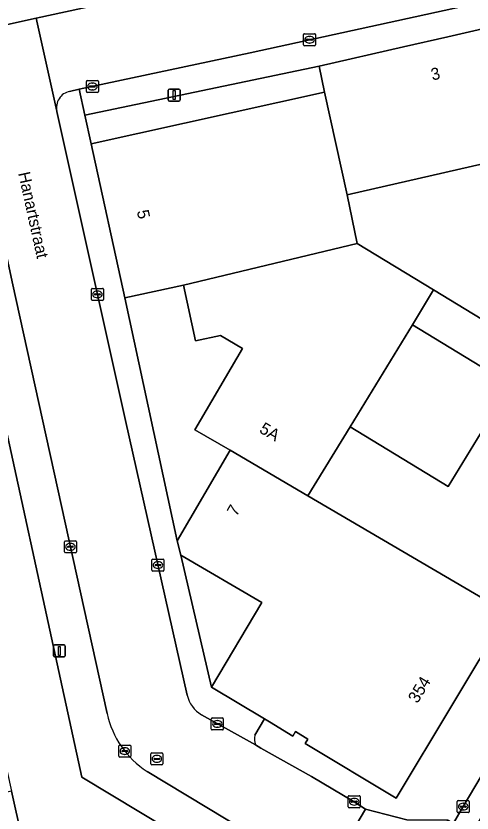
# Model space of a CAD drawing. Extents: x 160554 to 161248, y 385329 to 386506.
# Drawn here: x 160800.8 to 160838.9, y 385796.5 to 385863.1 of the extents above; entities that cross this region are included whole.
import ezdxf

# ---------------------------------------------------------------- set-up
doc = ezdxf.new("R2010")
doc.units = 0
for name, color, linetype in [('IMGEO_Erf', 7, 'Continuous'), ('IMGEO_Kolk', 7, 'Continuous'), ('IMGEO_Lichtmast', 7, 'Continuous'), ('IMGEO_Openbare_ruimte_label', 7, 'Continuous'), ('IMGEO_Pand', 7, 'Continuous'), ('IMGEO_Pand_nummerreeks', 7, 'Continuous'), ('IMGEO_Parkeervlak_open', 7, 'Continuous'), ('IMGEO_Rijbaan_lokaal_gesloten', 7, 'Continuous'), ('IMGEO_Rijbaan_lokaal_open', 7, 'Continuous'), ('IMGEO_Rioolput', 7, 'Continuous'), ('IMGEO_Voetpad_open', 7, 'Continuous')]:
    doc.layers.add(name, color=color, linetype=linetype)

msp = doc.modelspace()

# ---------------------------------------------------------------- linework, layer by layer
at = {"layer": 'IMGEO_Erf'}
for points in [[(160807.109, 385852.398), (160826.584, 385856.714), (160826.13, 385858.866), (160806.576, 385854.787)], [(160797.582, 385839.533), (160777.43, 385835.122), (160782.162, 385813.51), (160796.35, 385816.614), (160798.295, 385807.928), (160800.447, 385798.314), (160802.235, 385790.33), (160796.019, 385788.976), (160795.316, 385792.204), (160792.549, 385791.601), (160793.252, 385788.373), (160788.797, 385787.403), (160789.812, 385782.742), (160805.036, 385786.057), (160815.262, 385788.283), (160813.432, 385789.365), (160815.971, 385793.66), (160806.321, 385799.472)], [(160833.933, 385837.28), (160828.736, 385828.761), (160836.918, 385823.769), (160842.119, 385832.293)]]:
    msp.add_lwpolyline(points, close=True, dxfattribs=at)
msp.add_lwpolyline([(160844.796, 385851.869), (160828.488, 385848.132), (160829.322, 385844.074), (160835.706, 385840.185), (160845.725, 385834.081)], dxfattribs=at)
at = {"layer": 'IMGEO_Kolk'}
for p, q in [((160824.839, 385860.661), (160824.839, 385861.513)), ((160824.914, 385861.587), (160825.766, 385861.587)), ((160825.327, 385861.367), (160825.352, 385861.367)), ((160825.84, 385861.513), (160825.84, 385860.661)), ((160825.098, 385861.081), (160825.098, 385861.093)), ((160825.536, 385861.044), (160825.138, 385861.044)), ((160825.141, 385861.13), (160825.539, 385861.13)), ((160825.35, 385860.807), (160825.325, 385860.807)), ((160825.582, 385861.093), (160825.582, 385861.081)), ((160825.766, 385860.587), (160824.914, 385860.587)), ((160806.699, 385856.751), (160806.699, 385857.603)), ((160806.774, 385857.677), (160807.626, 385857.677)), ((160807.187, 385857.457), (160807.212, 385857.457)), ((160807.7, 385857.603), (160807.7, 385856.751)), ((160807.626, 385856.677), (160806.774, 385856.677)), ((160806.958, 385857.171), (160806.958, 385857.183)), ((160807.396, 385857.134), (160806.998, 385857.134)), ((160807.001, 385857.22), (160807.399, 385857.22)), ((160807.21, 385856.897), (160807.185, 385856.897)), ((160807.442, 385857.183), (160807.442, 385857.171)), ((160807.122, 385839.386), (160807.122, 385840.238)), ((160807.197, 385840.312), (160808.049, 385840.312)), ((160807.61, 385840.092), (160807.635, 385840.092)), ((160808.123, 385840.238), (160808.123, 385839.386)), ((160808.049, 385839.312), (160807.197, 385839.312)), ((160807.381, 385839.806), (160807.381, 385839.818)), ((160807.819, 385839.769), (160807.421, 385839.769)), ((160807.424, 385839.855), (160807.822, 385839.855)), ((160807.633, 385839.532), (160807.608, 385839.532)), ((160807.865, 385839.818), (160807.865, 385839.806)), ((160804.867, 385818.301), (160804.867, 385819.153)), ((160804.942, 385819.227), (160805.794, 385819.227)), ((160805.126, 385818.721), (160805.126, 385818.733)), ((160805.564, 385818.684), (160805.166, 385818.684)), ((160805.169, 385818.77), (160805.567, 385818.77)), ((160805.355, 385819.007), (160805.38, 385819.007)), ((160805.61, 385818.733), (160805.61, 385818.721)), ((160805.868, 385819.153), (160805.868, 385818.301)), ((160805.794, 385818.227), (160804.942, 385818.227)), ((160805.378, 385818.447), (160805.353, 385818.447)), ((160812.178, 385816.775), (160812.178, 385817.627)), ((160812.253, 385817.701), (160813.105, 385817.701)), ((160812.666, 385817.481), (160812.691, 385817.481)), ((160813.179, 385817.627), (160813.179, 385816.775)), ((160813.105, 385816.701), (160812.253, 385816.701)), ((160812.437, 385817.195), (160812.437, 385817.207)), ((160812.875, 385817.158), (160812.477, 385817.158)), ((160812.48, 385817.244), (160812.878, 385817.244)), ((160812.689, 385816.921), (160812.664, 385816.921)), ((160812.921, 385817.207), (160812.921, 385817.195)), ((160817.136, 385803.503), (160817.136, 385804.355)), ((160817.211, 385804.429), (160818.063, 385804.429)), ((160817.624, 385804.209), (160817.649, 385804.209)), ((160818.137, 385804.355), (160818.137, 385803.503)), ((160818.063, 385803.429), (160817.211, 385803.429)), ((160817.395, 385803.923), (160817.395, 385803.935)), ((160817.833, 385803.886), (160817.435, 385803.886)), ((160817.438, 385803.972), (160817.836, 385803.972)), ((160817.647, 385803.649), (160817.622, 385803.649)), ((160817.879, 385803.935), (160817.879, 385803.923)), ((160809.408, 385801.238), (160809.408, 385802.09)), ((160809.483, 385802.164), (160810.335, 385802.164)), ((160810.409, 385802.09), (160810.409, 385801.238)), ((160809.667, 385801.658), (160809.667, 385801.67)), ((160810.105, 385801.621), (160809.707, 385801.621)), ((160809.71, 385801.707), (160810.108, 385801.707)), ((160809.919, 385801.384), (160809.894, 385801.384)), ((160809.896, 385801.944), (160809.921, 385801.944)), ((160810.151, 385801.67), (160810.151, 385801.658)), ((160810.335, 385801.164), (160809.483, 385801.164)), ((160828.569, 385797.011), (160828.569, 385797.863)), ((160828.644, 385797.937), (160829.496, 385797.937)), ((160828.828, 385797.431), (160828.828, 385797.443)), ((160829.266, 385797.394), (160828.868, 385797.394)), ((160828.871, 385797.48), (160829.269, 385797.48)), ((160829.057, 385797.717), (160829.082, 385797.717)), ((160829.312, 385797.443), (160829.312, 385797.431)), ((160829.57, 385797.863), (160829.57, 385797.011)), ((160837.677, 385796.598), (160837.677, 385797.45)), ((160837.752, 385797.524), (160838.604, 385797.524)), ((160838.678, 385797.45), (160838.678, 385796.598)), ((160829.496, 385796.937), (160828.644, 385796.937)), ((160829.08, 385797.157), (160829.055, 385797.157)), ((160837.936, 385797.018), (160837.936, 385797.03)), ((160838.374, 385796.981), (160837.976, 385796.981)), ((160837.979, 385797.067), (160838.377, 385797.067)), ((160838.188, 385796.744), (160838.163, 385796.744)), ((160838.165, 385797.304), (160838.19, 385797.304)), ((160838.42, 385797.03), (160838.42, 385797.018)), ((160838.604, 385796.524), (160837.752, 385796.524))]:
    msp.add_line(p, q, dxfattribs=at)
for points in [[(160824.839, 385860.661), (160824.839, 385861.513)], [(160824.914, 385861.587), (160825.766, 385861.587)], [(160825.84, 385861.513), (160825.84, 385860.661)], [(160825.766, 385860.587), (160824.914, 385860.587)], [(160806.699, 385856.751), (160806.699, 385857.603)], [(160806.774, 385857.677), (160807.626, 385857.677)], [(160807.7, 385857.603), (160807.7, 385856.751)], [(160807.626, 385856.677), (160806.774, 385856.677)], [(160807.122, 385839.386), (160807.122, 385840.238)], [(160807.197, 385840.312), (160808.049, 385840.312)], [(160808.123, 385840.238), (160808.123, 385839.386)], [(160808.049, 385839.312), (160807.197, 385839.312)], [(160804.867, 385818.301), (160804.867, 385819.153)], [(160804.942, 385819.227), (160805.794, 385819.227)], [(160805.868, 385819.153), (160805.868, 385818.301)], [(160805.794, 385818.227), (160804.942, 385818.227)], [(160812.178, 385816.775), (160812.178, 385817.627)], [(160812.253, 385817.701), (160813.105, 385817.701)], [(160813.179, 385817.627), (160813.179, 385816.775)], [(160813.105, 385816.701), (160812.253, 385816.701)], [(160817.136, 385803.503), (160817.136, 385804.355)], [(160817.211, 385804.429), (160818.063, 385804.429)], [(160818.137, 385804.355), (160818.137, 385803.503)], [(160818.063, 385803.429), (160817.211, 385803.429)], [(160809.408, 385801.238), (160809.408, 385802.09)], [(160809.483, 385802.164), (160810.335, 385802.164)], [(160810.409, 385802.09), (160810.409, 385801.238)], [(160810.335, 385801.164), (160809.483, 385801.164)], [(160828.569, 385797.011), (160828.569, 385797.863)], [(160828.644, 385797.937), (160829.496, 385797.937)], [(160829.57, 385797.863), (160829.57, 385797.011)], [(160837.677, 385796.598), (160837.677, 385797.45)], [(160837.752, 385797.524), (160838.604, 385797.524)], [(160838.678, 385797.45), (160838.678, 385796.598)], [(160829.496, 385796.937), (160828.644, 385796.937)], [(160838.604, 385796.524), (160837.752, 385796.524)]]:
    msp.add_lwpolyline(points, dxfattribs=at)
for centre, radius, start, end in [((160824.916, 385861.511), 0.0765, 91.55205, 178.44795), ((160824.916, 385861.511), 0.0765, 91.55205, 178.44795), ((160825.764, 385861.511), 0.0765, 1.55205, 88.44795), ((160825.764, 385861.511), 0.0765, 1.55205, 88.44795), ((160824.916, 385860.663), 0.0765, 181.55205, 268.44795), ((160824.916, 385860.663), 0.0765, 181.55205, 268.44795), ((160825.138, 385861.09), 0.0403, 85.87752, 175.75265), ((160825.135, 385861.08), 0.0366, 178.93798, 274.71019), ((160825.539, 385861.087), 0.043, 264.86636, 352.45326), ((160825.543, 385861.092), 0.0386, 1.73085, 96.63898), ((160825.764, 385860.663), 0.0765, 271.55205, 358.44795), ((160825.764, 385860.663), 0.0765, 271.55205, 358.44795), ((160806.776, 385857.601), 0.0765, 91.55205, 178.44795), ((160806.776, 385857.601), 0.0765, 91.55205, 178.44795), ((160807.624, 385857.601), 0.0765, 1.55205, 88.44795), ((160807.624, 385857.601), 0.0765, 1.55205, 88.44795), ((160806.776, 385856.753), 0.0765, 181.55205, 268.44795), ((160806.776, 385856.753), 0.0765, 181.55205, 268.44795), ((160806.998, 385857.18), 0.0403, 85.87752, 175.75265), ((160806.995, 385857.17), 0.0366, 178.93798, 274.71019), ((160807.399, 385857.177), 0.043, 264.86636, 352.45326), ((160807.403, 385857.182), 0.0386, 1.73085, 96.63898), ((160807.624, 385856.753), 0.0765, 271.55205, 358.44795), ((160807.624, 385856.753), 0.0765, 271.55205, 358.44795), ((160807.199, 385840.236), 0.0765, 91.55205, 178.44795), ((160807.199, 385840.236), 0.0765, 91.55205, 178.44795), ((160808.047, 385840.236), 0.0765, 1.55205, 88.44795), ((160808.047, 385840.236), 0.0765, 1.55205, 88.44795), ((160807.199, 385839.388), 0.0765, 181.55205, 268.44795), ((160807.199, 385839.388), 0.0765, 181.55205, 268.44795), ((160807.421, 385839.815), 0.0403, 85.87752, 175.75265), ((160807.418, 385839.805), 0.0366, 178.93798, 274.71019), ((160807.822, 385839.812), 0.043, 264.86636, 352.45326), ((160807.826, 385839.817), 0.0386, 1.73085, 96.63898), ((160808.047, 385839.388), 0.0765, 271.55205, 358.44795), ((160808.047, 385839.388), 0.0765, 271.55205, 358.44795), ((160804.944, 385819.151), 0.0765, 91.55205, 178.44795), ((160804.944, 385819.151), 0.0765, 91.55205, 178.44795), ((160805.166, 385818.73), 0.0403, 85.87752, 175.75265), ((160805.163, 385818.72), 0.0366, 178.93798, 274.71019), ((160805.567, 385818.727), 0.043, 264.86636, 352.45326), ((160805.571, 385818.732), 0.0386, 1.73085, 96.63898), ((160805.792, 385819.151), 0.0765, 1.55205, 88.44795), ((160805.792, 385819.151), 0.0765, 1.55205, 88.44795), ((160804.944, 385818.303), 0.0765, 181.55205, 268.44795), ((160804.944, 385818.303), 0.0765, 181.55205, 268.44795), ((160805.792, 385818.303), 0.0765, 271.55205, 358.44795), ((160805.792, 385818.303), 0.0765, 271.55205, 358.44795), ((160812.255, 385817.625), 0.0765, 91.55205, 178.44795), ((160812.255, 385817.625), 0.0765, 91.55205, 178.44795), ((160813.103, 385817.625), 0.0765, 1.55205, 88.44795), ((160813.103, 385817.625), 0.0765, 1.55205, 88.44795), ((160812.255, 385816.777), 0.0765, 181.55205, 268.44795), ((160812.255, 385816.777), 0.0765, 181.55205, 268.44795), ((160812.477, 385817.204), 0.0403, 85.87752, 175.75265), ((160812.474, 385817.194), 0.0366, 178.93798, 274.71019), ((160812.878, 385817.201), 0.043, 264.86636, 352.45326), ((160812.882, 385817.206), 0.0386, 1.73085, 96.63898), ((160813.103, 385816.777), 0.0765, 271.55205, 358.44795), ((160813.103, 385816.777), 0.0765, 271.55205, 358.44795), ((160817.213, 385804.353), 0.0765, 91.55205, 178.44795), ((160817.213, 385804.353), 0.0765, 91.55205, 178.44795), ((160818.061, 385804.353), 0.0765, 1.55205, 88.44795), ((160818.061, 385804.353), 0.0765, 1.55205, 88.44795), ((160817.213, 385803.505), 0.0765, 181.55205, 268.44795), ((160817.213, 385803.505), 0.0765, 181.55205, 268.44795), ((160817.435, 385803.932), 0.0403, 85.87752, 175.75265), ((160817.432, 385803.922), 0.0366, 178.93798, 274.71019), ((160817.836, 385803.929), 0.043, 264.86636, 352.45326), ((160817.84, 385803.934), 0.0386, 1.73085, 96.63898), ((160818.061, 385803.505), 0.0765, 271.55205, 358.44795), ((160818.061, 385803.505), 0.0765, 271.55205, 358.44795), ((160809.485, 385802.088), 0.0765, 91.55205, 178.44795), ((160809.485, 385802.088), 0.0765, 91.55205, 178.44795), ((160810.333, 385802.088), 0.0765, 1.55205, 88.44795), ((160810.333, 385802.088), 0.0765, 1.55205, 88.44795), ((160809.707, 385801.667), 0.0403, 85.87752, 175.75265), ((160809.704, 385801.657), 0.0366, 178.93798, 274.71019), ((160810.108, 385801.664), 0.043, 264.86636, 352.45326), ((160810.112, 385801.669), 0.0386, 1.73085, 96.63898), ((160809.485, 385801.24), 0.0765, 181.55205, 268.44795), ((160809.485, 385801.24), 0.0765, 181.55205, 268.44795), ((160810.333, 385801.24), 0.0765, 271.55205, 358.44795), ((160810.333, 385801.24), 0.0765, 271.55205, 358.44795), ((160828.646, 385797.861), 0.0765, 91.55205, 178.44795), ((160828.646, 385797.861), 0.0765, 91.55205, 178.44795), ((160828.868, 385797.44), 0.0403, 85.87752, 175.75265), ((160828.865, 385797.43), 0.0366, 178.93798, 274.71019), ((160829.269, 385797.437), 0.043, 264.86636, 352.45326), ((160829.273, 385797.442), 0.0386, 1.73085, 96.63898), ((160829.494, 385797.861), 0.0765, 1.55205, 88.44795), ((160829.494, 385797.861), 0.0765, 1.55205, 88.44795), ((160837.754, 385797.448), 0.0765, 91.55205, 178.44795), ((160837.754, 385797.448), 0.0765, 91.55205, 178.44795), ((160838.602, 385797.448), 0.0765, 1.55205, 88.44795), ((160838.602, 385797.448), 0.0765, 1.55205, 88.44795), ((160828.646, 385797.013), 0.0765, 181.55205, 268.44795), ((160828.646, 385797.013), 0.0765, 181.55205, 268.44795), ((160829.494, 385797.013), 0.0765, 271.55205, 358.44795), ((160829.494, 385797.013), 0.0765, 271.55205, 358.44795), ((160837.976, 385797.027), 0.0403, 85.87752, 175.75265), ((160837.973, 385797.017), 0.0366, 178.93798, 274.71019), ((160838.377, 385797.024), 0.043, 264.86636, 352.45326), ((160838.381, 385797.029), 0.0386, 1.73085, 96.63898), ((160837.754, 385796.6), 0.0765, 181.55205, 268.44795), ((160837.754, 385796.6), 0.0765, 181.55205, 268.44795), ((160838.602, 385796.6), 0.0765, 271.55205, 358.44795), ((160838.602, 385796.6), 0.0765, 271.55205, 358.44795)]:
    msp.add_arc(centre, radius, start, end, dxfattribs=at)
for centre, major_axis, ratio, start_param, end_param in [((160825.326, 385861.087), (-0.387, 0.002), 0.722429, 4.712389, 7.853982), ((160825.351, 385861.087), (-0.39, 0.002), 0.717154, 1.570796, 4.712389), ((160807.186, 385857.177), (-0.387, 0.002), 0.722429, 4.712389, 7.853982), ((160807.211, 385857.177), (-0.39, 0.002), 0.717154, 1.570796, 4.712389), ((160807.609, 385839.812), (-0.387, 0.002), 0.722429, 4.712389, 7.853982), ((160807.634, 385839.812), (-0.39, 0.002), 0.717154, 1.570796, 4.712389), ((160805.354, 385818.727), (-0.387, 0.002), 0.722429, 4.712389, 7.853982), ((160805.379, 385818.727), (-0.39, 0.002), 0.717154, 1.570796, 4.712389), ((160812.665, 385817.201), (-0.387, 0.002), 0.722429, 4.712389, 7.853982), ((160812.69, 385817.201), (-0.39, 0.002), 0.717154, 1.570796, 4.712389), ((160817.623, 385803.929), (-0.387, 0.002), 0.722429, 4.712389, 7.853982), ((160817.648, 385803.929), (-0.39, 0.002), 0.717154, 1.570796, 4.712389), ((160809.895, 385801.664), (-0.387, 0.002), 0.722429, 4.712389, 7.853982), ((160809.92, 385801.664), (-0.39, 0.002), 0.717154, 1.570796, 4.712389), ((160829.056, 385797.437), (-0.387, 0.002), 0.722429, 4.712389, 7.853982), ((160829.081, 385797.437), (-0.39, 0.002), 0.717154, 1.570796, 4.712389), ((160838.164, 385797.024), (-0.387, 0.002), 0.722429, 4.712389, 7.853982), ((160838.189, 385797.024), (-0.39, 0.002), 0.717154, 1.570796, 4.712389)]:
    msp.add_ellipse(centre, major_axis=major_axis, ratio=ratio, start_param=start_param, end_param=end_param, dxfattribs=at)
at = {"layer": 'IMGEO_Lichtmast'}
for p, q in [((160813.542, 385856.057), (160813.542, 385856.857)), ((160813.542, 385856.857), (160813.542, 385856.057)), ((160813.642, 385856.957), (160814.432, 385856.957)), ((160814.432, 385856.957), (160813.642, 385856.957)), ((160814.532, 385856.857), (160814.532, 385856.057)), ((160814.532, 385856.057), (160814.532, 385856.857)), ((160814.432, 385855.957), (160813.642, 385855.957)), ((160813.642, 385855.957), (160814.432, 385855.957)), ((160803.948, 385809.627), (160803.948, 385810.427)), ((160803.948, 385810.427), (160803.948, 385809.627)), ((160804.048, 385810.527), (160804.838, 385810.527)), ((160804.838, 385810.527), (160804.048, 385810.527)), ((160804.938, 385810.427), (160804.938, 385809.627)), ((160804.938, 385809.627), (160804.938, 385810.427)), ((160804.838, 385809.527), (160804.048, 385809.527)), ((160804.048, 385809.527), (160804.838, 385809.527))]:
    msp.add_line(p, q, dxfattribs=at)
for points in [[(160813.962, 385856.832), (160814.112, 385856.832), (160814.112, 385856.082), (160813.962, 385856.082), (160813.962, 385856.832)], [(160804.368, 385810.402), (160804.518, 385810.402), (160804.518, 385809.652), (160804.368, 385809.652), (160804.368, 385810.402)]]:
    msp.add_lwpolyline(points, dxfattribs=at)
for centre, start, end in [((160813.642, 385856.857), 90, 180), ((160813.642, 385856.857), 90, 180), ((160814.432, 385856.857), 0, 90), ((160814.432, 385856.857), 360, 90), ((160813.642, 385856.057), 180, 270), ((160813.642, 385856.057), 180, 270), ((160814.432, 385856.057), 270, 0), ((160814.432, 385856.057), 270, 0), ((160804.048, 385810.427), 90, 180), ((160804.048, 385810.427), 90, 180), ((160804.838, 385810.427), 0, 90), ((160804.838, 385810.427), 360, 90), ((160804.048, 385809.627), 180, 270), ((160804.048, 385809.627), 180, 270), ((160804.838, 385809.627), 270, 0), ((160804.838, 385809.627), 270, 0)]:
    msp.add_arc(centre, 0.1, start, end, dxfattribs=at)
at = {"layer": 'IMGEO_Pand'}
for points in [[(160844.796, 385851.869), (160846.169, 385854.175), (160844.138, 385862.995), (160836.876, 385861.33), (160833.192, 385860.485), (160826.13, 385858.866), (160826.584, 385856.714), (160828.488, 385848.132)], [(160828.488, 385848.132), (160826.584, 385856.714), (160807.109, 385852.398), (160809.898, 385839.522), (160814.805, 385840.585), (160829.322, 385844.074)], [(160833.933, 385837.28), (160835.706, 385840.185), (160829.322, 385844.074), (160814.805, 385840.585), (160815.815, 385835.924), (160817.907, 385836.377), (160819.744, 385835.302), (160815.769, 385828.509), (160818.703, 385826.792), (160825.208, 385822.979), (160828.736, 385828.761)], [(160850.362, 385827.272), (160848.141, 385828.625), (160849.91, 385831.532), (160845.725, 385834.081), (160835.706, 385840.185), (160833.933, 385837.28), (160842.119, 385832.293), (160836.918, 385823.769), (160828.736, 385828.761), (160825.208, 385822.979), (160841.881, 385813.208), (160842.023, 385813.444), (160840.849, 385814.159), (160842.409, 385816.721), (160843.57, 385816.014)], [(160841.881, 385813.208), (160825.208, 385822.979), (160818.703, 385826.792), (160814.274, 385819.222), (160814.586, 385818.033), (160821.361, 385814.069), (160817.141, 385807.014), (160821.577, 385804.345), (160821.993, 385804.095), (160823.943, 385802.922), (160824.166, 385803.292), (160825.188, 385802.664), (160824.972, 385802.304), (160832.568, 385797.734)], [(160802.235, 385790.33), (160800.447, 385798.314), (160772.013, 385792.125), (160774.791, 385779.47), (160789.812, 385782.742), (160788.797, 385787.403), (160793.252, 385788.373), (160792.549, 385791.601), (160795.316, 385792.204), (160796.019, 385788.976)]]:
    msp.add_lwpolyline(points, close=True, dxfattribs=at)
at = {"layer": 'IMGEO_Parkeervlak_open'}
for points in [[(160860.8, 385878.948), (160852.254, 385877.078), (160847.594, 385876.059), (160832.965, 385872.859), (160820.576, 385870.148), (160812.794, 385868.446), (160796.008, 385864.76), (160795.385, 385864.625), (160796.064, 385861.476), (160802.504, 385862.88), (160823.141, 385867.378), (160842.527, 385871.618), (160855.448, 385874.495)], [(160856.882, 385867.979), (160849.724, 385866.434), (160820.371, 385859.999), (160806.095, 385856.942), (160806.576, 385854.787), (160826.13, 385858.866), (160833.192, 385860.485), (160836.876, 385861.33)], [(160836.876, 385861.33), (160844.138, 385862.995), (160846.968, 385863.605), (160858.978, 385866.377), (160860.16, 385866.655), (160865.046, 385865.05), (160865.169, 385865.426), (160870.459, 385863.696), (160871.183, 385865.245), (160869.21, 385865.911), (160864.479, 385867.645)], [(160796.064, 385861.476), (160795.385, 385864.625), (160792.241, 385863.947), (160792.688, 385861.904), (160794.287, 385854.597), (160795.61, 385848.538), (160795.644, 385848.382), (160797.582, 385839.533), (160806.321, 385799.472), (160815.971, 385793.66), (160818.326, 385792.268), (160824.271, 385788.754), (160825.347, 385790.624)], [(160808.431, 385804.793), (160800.508, 385840.854), (160796.064, 385861.476)], [(160809.898, 385839.522), (160807.109, 385852.398), (160806.576, 385854.787), (160806.095, 385856.942), (160805.303, 385856.772)], [(160804.23, 385855.101), (160809.958, 385829.285), (160815.123, 385806.338)], [(160820.769, 385802.982), (160821.577, 385804.345), (160817.141, 385807.014), (160814.586, 385818.033), (160814.274, 385819.222), (160809.898, 385839.522)], [(160816.317, 385804.701), (160820.814, 385802.173)], [(160826.58, 385791.032), (160811.768, 385799.966)]]:
    msp.add_lwpolyline(points, dxfattribs=at)
for points in [[(160814.274, 385819.222), (160818.703, 385826.792), (160815.769, 385828.509), (160819.744, 385835.302), (160817.907, 385836.377), (160815.815, 385835.924), (160814.805, 385840.585), (160809.898, 385839.522)], [(160817.141, 385807.014), (160821.361, 385814.069), (160814.586, 385818.033)]]:
    msp.add_lwpolyline(points, close=True, dxfattribs=at)
for centre, radius, start, end in [((160805.597, 385855.403), 1.4, 102.10845, 192.48004), ((160817.616, 385806.903), 2.556, 192.75896, 239.45379), ((160815.988, 385806.451), 7.737, 192.37065, 236.94308), ((160822.13, 385802.652), 1.4, 166.36467, 200.00283)]:
    msp.add_arc(centre, radius, start, end, dxfattribs=at)
at = {"layer": 'IMGEO_Rijbaan_lokaal_gesloten'}
msp.add_lwpolyline([(160824.538, 385774.128), (160826.04, 385773.231), (160868.007, 385843.619), (160866.508, 385844.523), (160866.264, 385844.178), (160857.435, 385829.369), (160848.222, 385813.893), (160841.702, 385802.983), (160838.179, 385797.023), (160837.349, 385795.634), (160831.171, 385785.249), (160827.643, 385779.323)], close=True, dxfattribs=at)
at = {"layer": 'IMGEO_Rijbaan_lokaal_open'}
for points in [[(160855.448, 385874.495), (160842.527, 385871.618), (160823.141, 385867.378), (160802.504, 385862.88), (160804.222, 385855.128), (160804.23, 385855.101)], [(160805.303, 385856.772), (160806.095, 385856.942), (160820.371, 385859.999), (160849.724, 385866.434), (160856.882, 385867.979)], [(160804.23, 385855.101), (160804.222, 385855.128), (160802.504, 385862.88), (160796.064, 385861.476), (160800.508, 385840.854), (160808.431, 385804.793)], [(160815.123, 385806.338), (160809.958, 385829.285), (160804.23, 385855.101)], [(160811.768, 385799.966), (160826.58, 385791.032), (160830.011, 385796.806), (160829.07, 385797.436), (160825.508, 385799.535), (160821.27, 385801.917), (160820.814, 385802.173), (160816.317, 385804.701)]]:
    msp.add_lwpolyline(points, dxfattribs=at)
for centre, radius, start, end in [((160805.597, 385855.403), 1.4, 102.10845, 192.48004), ((160817.616, 385806.903), 2.556, 192.75896, 239.45379), ((160815.988, 385806.451), 7.737, 192.37065, 236.94308)]:
    msp.add_arc(centre, radius, start, end, dxfattribs=at)
at = {"layer": 'IMGEO_Rioolput'}
for p, q in [((160812.086, 385800.588), (160812.086, 385801.44)), ((160812.161, 385801.514), (160813.013, 385801.514)), ((160813.087, 385801.44), (160813.087, 385800.588)), ((160812.345, 385801.008), (160812.345, 385801.02)), ((160812.783, 385800.971), (160812.385, 385800.971)), ((160812.388, 385801.057), (160812.786, 385801.057)), ((160812.597, 385800.734), (160812.572, 385800.734)), ((160812.574, 385801.294), (160812.599, 385801.294)), ((160812.829, 385801.02), (160812.829, 385801.008)), ((160813.013, 385800.514), (160812.161, 385800.514))]:
    msp.add_line(p, q, dxfattribs=at)
for points in [[(160812.086, 385800.588), (160812.086, 385801.44)], [(160812.161, 385801.514), (160813.013, 385801.514)], [(160813.087, 385801.44), (160813.087, 385800.588)], [(160813.013, 385800.514), (160812.161, 385800.514)]]:
    msp.add_lwpolyline(points, dxfattribs=at)
for centre, radius, start, end in [((160812.163, 385801.438), 0.0765, 91.55205, 178.44795), ((160812.163, 385801.438), 0.0765, 91.55205, 178.44795), ((160813.011, 385801.438), 0.0765, 1.55205, 88.44795), ((160813.011, 385801.438), 0.0765, 1.55205, 88.44795), ((160812.385, 385801.017), 0.0403, 85.87752, 175.75265), ((160812.382, 385801.007), 0.0366, 178.93798, 274.71019), ((160812.786, 385801.014), 0.043, 264.86636, 352.45326), ((160812.79, 385801.019), 0.0386, 1.73085, 96.63898), ((160812.163, 385800.59), 0.0765, 181.55205, 268.44795), ((160812.163, 385800.59), 0.0765, 181.55205, 268.44795), ((160813.011, 385800.59), 0.0765, 271.55205, 358.44795), ((160813.011, 385800.59), 0.0765, 271.55205, 358.44795)]:
    msp.add_arc(centre, radius, start, end, dxfattribs=at)
for centre, major_axis, ratio, start_param, end_param in [((160812.573, 385801.014), (-0.387, 0.002), 0.722429, 4.712389, 7.853982), ((160812.598, 385801.014), (-0.39, 0.002), 0.717154, 1.570796, 4.712389)]:
    msp.add_ellipse(centre, major_axis=major_axis, ratio=ratio, start_param=start_param, end_param=end_param, dxfattribs=at)
at = {"layer": 'IMGEO_Voetpad_open'}
for points in [[(160841.881, 385813.208), (160832.568, 385797.734), (160824.972, 385802.304), (160825.188, 385802.664), (160824.166, 385803.292), (160823.943, 385802.922), (160821.993, 385804.095), (160821.577, 385804.345), (160820.769, 385802.982)], [(160820.814, 385802.173), (160821.27, 385801.917), (160825.508, 385799.535), (160829.07, 385797.436), (160830.011, 385796.806), (160833.466, 385795.918), (160836.92, 385795.889), (160837.349, 385795.634), (160838.179, 385797.023), (160841.702, 385802.983)]]:
    msp.add_lwpolyline(points, dxfattribs=at)
msp.add_lwpolyline([(160836.92, 385795.889), (160833.466, 385795.918), (160830.011, 385796.806), (160826.58, 385791.032), (160830.742, 385785.504)], close=True, dxfattribs=at)
msp.add_arc((160822.13, 385802.652), 1.4, 166.36467, 200.00283, dxfattribs=at)

# ---------------------------------------------------------------- texts
at = {"layer": 'IMGEO_Openbare_ruimte_label'}
msp.add_text('Hanartstraat', height=1, rotation=282.41077, dxfattribs=at).set_placement((160800.999, 385849.935))
at = {"layer": 'IMGEO_Pand_nummerreeks'}
for s, rotation, p in [('3', 12.91396, (160835.599, 385857.672)), ('5', 282.22172, (160810.908, 385846.763)), ('5A', 329.63324, (160821.068, 385828.325)), ('7', 59.66782, (160819.238, 385821.211)), ('354', 58.95736, (160834.355, 385805.59))]:
    msp.add_text(s, height=1, rotation=rotation, dxfattribs=at).set_placement(p)

doc.saveas('drawing.dxf')
